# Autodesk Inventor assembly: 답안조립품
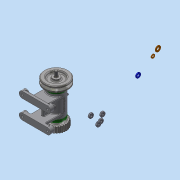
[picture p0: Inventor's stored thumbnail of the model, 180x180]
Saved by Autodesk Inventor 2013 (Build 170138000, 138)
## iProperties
Created: 2015-11
Part Number: 답안조립품
Document SubType Name: Assembly
Designer: Administrator
Author: Administrator
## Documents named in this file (16)
- C:\Users\Administrator\Desktop\451110V1010\답안조립품.iam
- C:\Users\Administrator\Desktop\451110V1010\V벨트풀리.ipt
- C:\Users\Administrator\Desktop\451110V1010\너트 M 8.ipt
- C:\Users\Administrator\Desktop\451110V1010\니플 M 6 x 0.75.ipt
- C:\Users\Administrator\Desktop\451110V1010\베어링 15 x 32 x 9.ipt
- C:\Users\Administrator\Desktop\451110V1010\본체.ipt
- C:\Users\Administrator\Desktop\451110V1010\볼트 M 6 x 8.ipt
- C:\Users\Administrator\Desktop\451110V1010\볼트 M4 x 12.ipt
- C:\Users\Administrator\Desktop\451110V1010\스퍼기어.ipt
- C:\Users\Administrator\Desktop\451110V1010\스프링와셔 8.ipt
- C:\Users\Administrator\Desktop\451110V1010\오일 실 15 25 7.ipt
- C:\Users\Administrator\Desktop\451110V1010\와셔 6x11.5.ipt
- C:\Users\Administrator\Desktop\451110V1010\와셔 8x17.ipt
- C:\Users\Administrator\Desktop\451110V1010\축.ipt
- C:\Users\Administrator\Desktop\451110V1010\커버.ipt
- C:\Users\Administrator\Desktop\451110V1010\키 3 x 3 x 12.ipt
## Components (11 placed, 3 different names)
1. V벨트풀리:1
2. KS B 2023 6002 - 15 x 32 x 9:1
3. KS B 2023 6002 - 15 x 32 x 9:2
4. ISO 4762 M4 x 12:1
5. ISO 4762 M4 x 12:3
6. ISO 4762 M4 x 12:4
7. ISO 4762 M4 x 12:5
8. ISO 4762 M4 x 12:2
9. ISO 4762 M4 x 12:6
10. ISO 4762 M4 x 12:7
11. ISO 4762 M4 x 12:8
